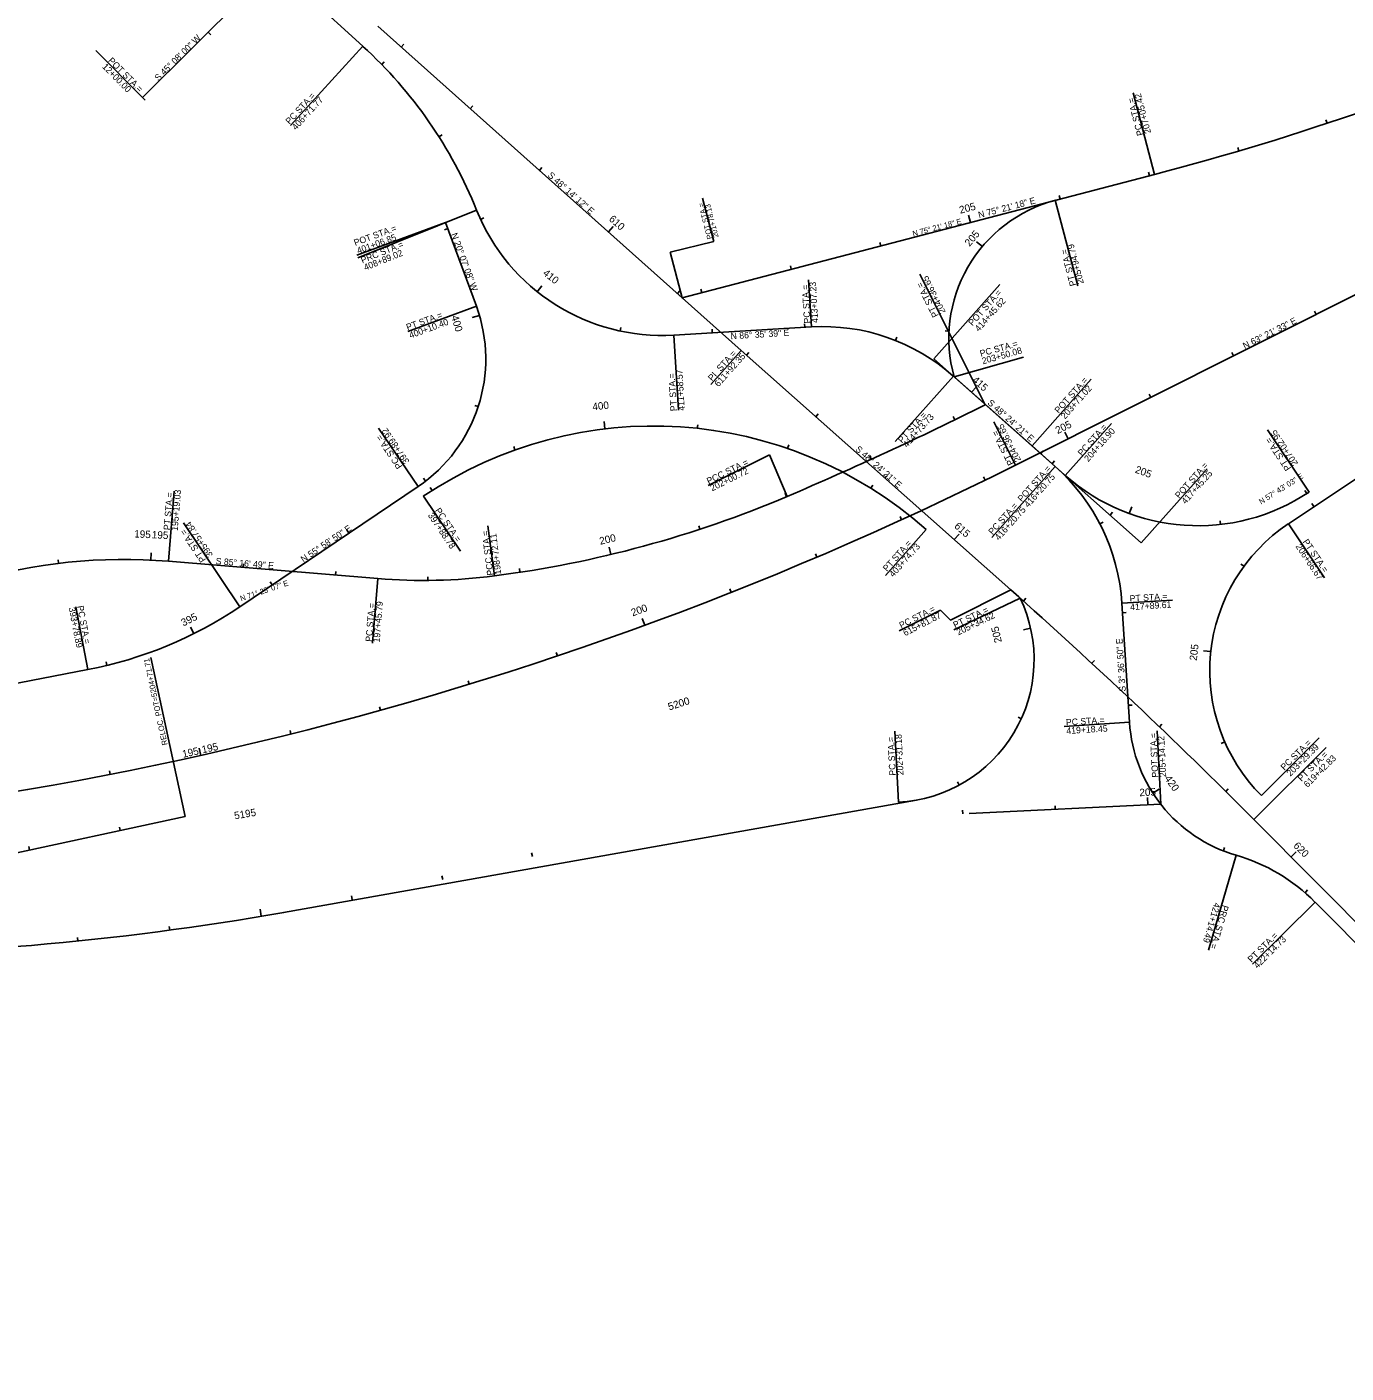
# Model space of a CAD drawing. Extents: x 1944333 to 1978554, y 788952 to 827675.
# Drawn here: x 1970666 to 1972091, y 801731 to 803186 of the extents above; entities that cross this region are included whole.
import ezdxf

# ---------------------------------------------------------------- set-up
doc = ezdxf.new("R2010")
doc.units = 0
for name, color, linetype in [('RD_HC_CL_Rel', 7, 'Continuous'), ('RD_HC_Data_Rel', 7, 'Continuous'), ('RD_HC_Data_Tic_Rel', 7, 'Continuous'), ('RD_HC_TX_Rel_Sta50', 7, 'Continuous')]:
    doc.layers.add(name, color=color, linetype=linetype)

msp = doc.modelspace()

# ---------------------------------------------------------------- linework, layer by layer
at = {"layer": 'RD_HC_CL_Rel'}
for p, q in [((1971733.6, 802712.2), (1977445.5, 805577.6)), ((1971733.6, 802712.2), (1977177.4, 805443.1)), ((1970666, 803495.5), (1971028.6, 803164.7)), ((1970933.3, 803251.6), (1970790.6, 803109.5)), ((1971044.7, 803186.4), (1971437.2, 802836)), ((1971373.4, 802893), (1971883.6, 803026.3)), ((1971151.2, 802883.8), (1971118, 802974.3)), ((1971364.6, 802852.6), (1971513, 802861.5)), ((1972028.2, 802648.8), (1972357, 802868.6)), ((1971437.2, 802836), (1971728.6, 802577.4)), ((1971645.3, 802827.1), (1971869.4, 802628.2)), ((1971666.4, 802808.4), (1971751.4, 802732.9)), ((1971751.4, 802732.9), (1971787.2, 802701.1)), ((1970895.8, 802559.2), (1971088.2, 802689.1)), ((1971824.7, 802648.6), (1971828.3, 802650.5)), ((1970818.6, 802608.3), (1971044.6, 802589.7)), ((1971848.5, 802562.9), (1971856.6, 802434.3)), ((1971849.2, 802552.5), (1971853.1, 802552.8)), ((1970421.7, 802431.5), (1970731.6, 802491.3)), ((1971855.5, 802452.7), (1971859.5, 802453)), ((1971881.8, 802357.7), (1971888.6, 802362)), ((1970943, 802228.9), (1971626.6, 802350.3)), ((1970416.5, 802242), (1970836.6, 802332.4)), ((1971683.3, 802335.8), (1971890.4, 802345.7)), ((1971990.8, 802329.4), (1972573.8, 801742.5)), ((1971949.8, 802297.9), (1971949.7, 802297.9)), ((1971958, 802295.4), (1971959.4, 802299.1)), ((1972046.2, 802250.2), (1972048.8, 802253.2)), ((1972057, 802240.1), (1972562.5, 801731.2))]:
    msp.add_line(p, q, dxfattribs=at)
for centre, radius, start, end in [((1971125.1, 805928.8), 3000, 284.6451, 293.8451), ((1970702.4, 802807.1), 484, 21.9066, 47.6252), ((1971351.8, 803068.3), 216, 201.9066, 273.4058), ((1971815.5, 802849.3), 154, 104.6451, 195.6897), ((1970995.3, 802826.7), 166, 304.0194, 20.119), ((1971525.6, 802649.9), 212, 48.4058, 93.4058), ((1970020.9, 806126.4), 3746.7, 293.033, 296.6408), ((1971342.3, 802310.5), 444, 48.4058, 124.0194), ((1970020.9, 806126.4), 3819.7, 269.5721, 296.6408), ((1970020.9, 806126.4), 3819.7, 269.5721, 296.6408), ((1971632.9, 802549.3), 216, 3.6139, 48.4058), ((1971930.6, 802862.7), 216, 228.4058, 303.7548), ((1971017.3, 803782.7), 1200, 277.3429, 293.033), ((1972134.3, 802490), 191, 123.7548, 224.9321), ((1970770.3, 802023.3), 587, 85.2802, 106.4681), ((1971094, 803187.6), 600, 265.2802, 277.3429), ((1971599.6, 802501.9), 154, 272.7416, 25.6376), ((1967911.4, 798277.1), 5750, 44.80908, 48.40581), ((1970647.4, 802927.2), 444, 280.9265, 304.0194), ((1972016.3, 802444.4), 160, 183.6139, 253.8155), ((1971916.5, 802100.6), 198, 44.8091, 73.8155), ((1970418.4, 805182.7), 3000, 269.5721, 280.0718)]:
    msp.add_arc(centre, radius, start, end, dxfattribs=at)
at = {"layer": 'RD_HC_Data_Rel'}
for p, q in [((1971028.6, 803164.7), (1970950.4, 803079)), ((1970740.2, 803160.1), (1970790.6, 803109.5)), ((1971883.6, 803026.3), (1971860.5, 803114.6)), ((1971151.4, 802987.7), (1971023.3, 802936.2)), ((1971407.6, 802953.7), (1971395.4, 803000.7)), ((1971776.5, 802998.3), (1971800.7, 802906)), ((1971118, 802974.3), (1971022.2, 802939.2)), ((1971407.6, 802953.7), (1971360.5, 802942.4)), ((1971373.4, 802893), (1971360.5, 802942.4)), ((1971700.9, 802777.4), (1971630.2, 802918.4)), ((1971513, 802861.5), (1971510, 802912.5)), ((1971645.3, 802827.1), (1971716.5, 802907.2)), ((1971151.2, 802883.8), (1971077.3, 802856.7)), ((1971364.6, 802852.6), (1971369.5, 802771.4)), ((1971437.2, 802836), (1971404.6, 802799.4)), ((1971667.2, 802807.7), (1971742.3, 802828.8)), ((1971666.4, 802808.4), (1971603.5, 802737.6)), ((1971751.4, 802732.9), (1971815.3, 802804.9)), ((1971733.6, 802712.2), (1971710.2, 802759)), ((1971787.2, 802701.1), (1971837.1, 802757.3)), ((1971088.2, 802689.1), (1971045.5, 802752.2)), ((1972050.6, 802683.1), (1972005.6, 802750.5)), ((1971401.6, 802690.3), (1971467.7, 802723.4)), ((1971486.8, 802678.4), (1971467.7, 802723.4)), ((1971776.3, 802710.8), (1971708.1, 802633.9)), ((1971773.1, 802713.7), (1971775.7, 802716.7)), ((1971869.4, 802628.2), (1971940.6, 802708.3)), ((1970818.6, 802608.3), (1970824.9, 802683.9)), ((1972048.2, 802681.5), (1972046, 802684.8)), ((1971093.9, 802678.5), (1971134, 802619.1)), ((1971856.4, 802659.8), (1971859.2, 802667.3)), ((1971954.9, 802648), (1971954.4, 802652)), ((1970895.8, 802559.2), (1970834.7, 802649.8)), ((1971170.7, 802592.5), (1971163.7, 802646.5)), ((1971637.1, 802642.5), (1971593, 802592.8)), ((1972028.2, 802648.8), (1972067.2, 802590.4)), ((1971044.6, 802589.7), (1971038.9, 802520)), ((1971738.5, 802568.6), (1971667, 802534.3)), ((1971848.5, 802562.9), (1971902.9, 802566.3)), ((1970731.6, 802491.3), (1970718.5, 802559.1)), ((1970836.6, 802332.4), (1970799.7, 802504.2)), ((1971856.6, 802434.3), (1971785.9, 802429.8)), ((1971607, 802348.1), (1971603.3, 802424.7)), ((1971890.4, 802345.7), (1971886.6, 802425)), ((1971990.8, 802329.4), (1972069.1, 802407.2)), ((1971999.1, 802355.1), (1972061.6, 802417.5)), ((1971876.3, 802345), (1971875.9, 802353)), ((1971971.7, 802290.7), (1971941.9, 802188.1)), ((1972057, 802240.1), (1971989.6, 802173.1))]:
    msp.add_line(p, q, dxfattribs=at)
for points in [[(1971728.6, 802577.4), (1971663.4, 802544.7), (1971652.6, 802555.4)], [(1971652.6, 802555.4), (1971608, 802533)]]:
    msp.add_lwpolyline(points, dxfattribs=at)
at = {"layer": 'RD_HC_Data_Tic_Rel'}
for p, q in [((1970861.5, 803180.1), (1970864.3, 803177.2)), ((1971070, 803163.9), (1971072.7, 803166.9)), ((1971048.9, 803145), (1971051.7, 803147.8)), ((1971048.9, 803145), (1971051.7, 803147.8)), ((1970790.6, 803109.5), (1970793.4, 803106.7)), ((1971144.6, 803097.3), (1971147.3, 803100.3)), ((1972070.1, 803081.5), (1972068.8, 803085.3)), ((1971110.8, 803066.8), (1971114.2, 803068.9)), ((1971110.8, 803066.8), (1971114.2, 803068.9)), ((1971974.7, 803051.6), (1971973.6, 803055.5)), ((1971219.2, 803030.7), (1971221.8, 803033.7)), ((1971878.3, 803024.9), (1971877.3, 803028.8)), ((1971781.6, 802999.6), (1971780.6, 803003.5)), ((1971155.8, 802977.6), (1971159.4, 802979.3)), ((1971684.8, 802974.3), (1971682.8, 802982.1)), ((1971120.3, 802967.9), (1971116.6, 802966.5)), ((1971293.8, 802964.1), (1971299.1, 802970)), ((1971588.1, 802949), (1971587.1, 802952.9)), ((1971697.7, 802948.5), (1971691.5, 802953.6)), ((1971491.3, 802923.8), (1971490.3, 802927.6)), ((1971216.9, 802899.6), (1971221.9, 802905.8)), ((1971368.4, 802897.5), (1971371, 802900.5)), ((1971394.6, 802898.5), (1971393.6, 802902.4)), ((1971154.4, 802873.9), (1971146.8, 802871.6)), ((1972058.4, 802875.1), (1972056.6, 802878.7)), ((1972058.4, 802875.1), (1972056.6, 802878.7)), ((1971306.4, 802857.1), (1971307.3, 802861)), ((1971406, 802855.1), (1971405.8, 802859.1)), ((1971505.8, 802861.1), (1971505.6, 802865)), ((1971661.7, 802857), (1971657.7, 802857.2)), ((1971603.9, 802846.9), (1971605.4, 802850.6)), ((1971443, 802830.9), (1971445.6, 802833.9)), ((1971969, 802830.3), (1971967.2, 802833.9)), ((1971969, 802830.3), (1971967.2, 802833.9)), ((1971686, 802791), (1971691.3, 802796.9)), ((1971686, 802791), (1971691.3, 802796.9)), ((1971879.6, 802785.4), (1971877.9, 802789)), ((1971879.6, 802785.4), (1971877.9, 802789)), ((1971153.2, 802775.4), (1971149.4, 802776.6)), ((1971290, 802751.4), (1971289.1, 802759.3)), ((1971389.8, 802751.9), (1971390.3, 802755.9)), ((1971517.8, 802764.5), (1971520.4, 802767.5)), ((1971668.1, 802761.2), (1971666.3, 802764.8)), ((1971790.3, 802740.6), (1971786.7, 802747.8)), ((1971790.3, 802740.6), (1971786.7, 802747.8)), ((1971192.9, 802728.6), (1971191.6, 802732.3)), ((1971487.2, 802730.2), (1971488.5, 802734)), ((1971760.8, 802724.6), (1971763.5, 802727.6)), ((1971760.8, 802724.6), (1971763.5, 802727.6)), ((1971760.8, 802724.6), (1971763.5, 802727.6)), ((1971760.8, 802724.6), (1971763.5, 802727.6)), ((1971760.8, 802724.6), (1971763.5, 802727.6)), ((1971577.7, 802718.4), (1971576, 802722.1)), ((1971773.1, 802713.7), (1971775.7, 802716.7)), ((1971096.3, 802695), (1971093.9, 802698.1)), ((1971592.5, 802698.1), (1971595.2, 802701.1)), ((1971700.8, 802695.9), (1971699, 802699.5)), ((1971700.8, 802695.9), (1971699, 802699.5)), ((1971103.3, 802684.6), (1971101.1, 802688)), ((1971486.2, 802678.1), (1971484.6, 802681.8)), ((1971577.3, 802687.2), (1971579.4, 802690.6)), ((1972055.9, 802667.4), (1972053.7, 802670.7)), ((1971610.4, 802653.1), (1971608.8, 802656.8)), ((1971610.4, 802653.1), (1971608.8, 802656.8)), ((1971835.6, 802658.2), (1971838.2, 802661.2)), ((1971835.6, 802658.2), (1971838.2, 802661.2)), ((1971835.6, 802658.2), (1971838.2, 802661.2)), ((1971013.6, 802638.8), (1971011.4, 802642.1)), ((1971392.6, 802642.9), (1971391.3, 802646.7)), ((1971667.3, 802631.7), (1971672.6, 802637.7)), ((1971296.4, 802615.6), (1971294.6, 802623.4)), ((1970699.8, 802606.1), (1970699.4, 802610)), ((1970799.7, 802609.6), (1970800.1, 802617.6)), ((1971519, 802612.7), (1971517.4, 802616.4)), ((1971519, 802612.7), (1971517.4, 802616.4)), ((1970899.3, 802601.7), (1970899.7, 802605.6)), ((1970999, 802593.4), (1970999.3, 802597.4)), ((1971198.3, 802596.4), (1971197.7, 802600.4)), ((1971980.3, 802603), (1971977, 802605.3)), ((1970930.7, 802582.8), (1970928.5, 802586.1)), ((1971098.8, 802587.6), (1971098.8, 802591.6)), ((1971426.5, 802574.7), (1971425, 802578.4)), ((1971426.5, 802574.7), (1971425, 802578.4)), ((1971742.1, 802565.3), (1971744.8, 802568.3)), ((1971742.1, 802565.3), (1971744.8, 802568.3)), ((1970845.9, 802530.1), (1970842.3, 802537.2)), ((1971333, 802539.1), (1971330.3, 802546.6)), ((1971333, 802539.1), (1971330.3, 802546.6)), ((1971749.8, 802535.9), (1971742, 802534.2)), ((1971238.7, 802506), (1971237.4, 802509.8)), ((1971238.7, 802506), (1971237.4, 802509.8)), ((1971944.4, 802510.8), (1971936.5, 802511.7)), ((1970752.2, 802495.8), (1970751.2, 802499.7)), ((1971816.1, 802498.1), (1971818.8, 802501)), ((1971143.5, 802475.4), (1971142.3, 802479.2)), ((1971143.5, 802475.4), (1971142.3, 802479.2)), ((1971047.5, 802447.2), (1971046.4, 802451.1)), ((1971047.5, 802447.2), (1971046.4, 802451.1)), ((1971739.8, 802438.2), (1971736.2, 802439.9)), ((1970950.9, 802421.6), (1970949.9, 802425.5)), ((1970950.9, 802421.6), (1970949.9, 802425.5)), ((1971888.9, 802429.5), (1971891.7, 802432.4)), ((1970853.6, 802398.5), (1970851.8, 802406.3)), ((1970853.6, 802398.5), (1970851.8, 802406.3)), ((1971959.5, 802413.1), (1971955.8, 802411.5)), ((1970755.7, 802378), (1970754.9, 802381.9)), ((1970755.7, 802378), (1970754.9, 802381.9)), ((1971672.7, 802366.4), (1971670.8, 802369.9)), ((1971960.5, 802359.7), (1971963.3, 802362.6)), ((1971676.5, 802335.4), (1971676.3, 802339.4)), ((1971776.4, 802340.2), (1971776.2, 802344.2)), ((1970766.5, 802317.3), (1970765.7, 802321.2)), ((1970668.7, 802296.3), (1970667.9, 802300.2)), ((1971211.7, 802289.5), (1971210.6, 802293.3)), ((1972031.1, 802288.9), (1972036.8, 802294.5)), ((1971114.8, 802264.6), (1971113.9, 802268.5)), ((1971017.2, 802243), (1971016.4, 802247)), ((1970918.9, 802224.7), (1970917.5, 802232.6)), ((1970720.7, 802198), (1970720.3, 802201.9)), ((1970820, 802209.7), (1970819.5, 802213.6))]:
    msp.add_line(p, q, dxfattribs=at)

# ---------------------------------------------------------------- texts
at = {"layer": 'RD_HC_CL_Rel'}
for s, rotation, p in [('PC STA.=', 48.4058, (1971708.7, 802636.4)), ('416+20.75', 48.4058, (1971715.6, 802630.3)), ('S 3%%d 36\' 50" E', 93.6139, (1971852.6, 802467.6)), ('PC STA.=', 3.6139, (1971788.2, 802430.8)), ('419+18.45', 3.6139, (1971788.7, 802421.6)), ('421+14.49', 253.8155, (1971948.3, 802240)), ('PRC STA.=', 253.8155, (1971957.2, 802237.4)), ('PT STA.=', 44.8091, (1971988.4, 802174.3)), ('422+14.73', 44.8091, (1971994.9, 802167.8))]:
    msp.add_text(s, height=7, rotation=rotation, dxfattribs=at).set_placement(p)
at = {"layer": 'RD_HC_Data_Rel'}
for s, height, rotation, p in [('S 45%%d 08\' 00" W', 7, 44.8665, (1970807.8, 803126.7)), ('POT STA.=', 7, 314.8665, (1970752.9, 803148.6)), ('12+00.00', 7, 314.8665, (1970746.4, 803142.1)), ('PC STA.=', 7, 47.6252, (1970949.5, 803079.8)), ('406+71.77', 7, 47.6252, (1970956.3, 803073.6)), ('PC STA.=', 7, 104.6451, (1971871.8, 803069.1)), ('207+05.42', 7, 104.6451, (1971880, 803071.3)), ('S 48%%d 14\' 12" E', 7, 318.2368, (1971227.7, 803024.5)), ('N 75%%d 21\' 18" E', 7, 14.6451, (1971694.2, 802979)), ('POT STA.=', 5.67, 104.6451, (1971406.3, 802957.1)), ('201+78.13', 5.67, 104.6451, (1971412.9, 802958.8)), ('N 75%%d 21\' 18" E', 6, 14.6451, (1971623.1, 802959.2)), ('POT STA.=', 7, 20.119, (1971020.4, 802948.9)), ('401+06.85', 7, 20.119, (1971023.6, 802940.3)), ('N 20%%d 07\' 08" W', 7, 290.119, (1971123.7, 802961.6)), ('PRC STA.=', 7, 21.9066, (1971028.1, 802930)), ('408+89.02', 7, 21.9066, (1971031.2, 802922.2)), ('PT STA.=', 7, 104.6451, (1971799.3, 802906.6)), ('205+94.79', 7, 104.6451, (1971807.4, 802908.7)), ('204+36.65', 7, 116.6408, (1971658.3, 802877.7)), ('PC STA.=', 7, 93.4058, (1971512.1, 802865.5)), ('413+07.23', 7, 93.4058, (1971520.5, 802866)), ('PT STA.=', 7, 116.6408, (1971650.7, 802874)), ('POT STA.=', 7, 48.4058, (1971687.1, 802862)), ('414+45.62', 7, 48.4058, (1971694, 802855.9)), ('PT STA.=', 7, 20.119, (1971076.9, 802857.6)), ('400+10.40', 7, 20.119, (1971080, 802848.9)), ('N 63%%d 21\' 33" E', 7, 26.6408, (1971981.2, 802837.5)), ('N 86%%d 35\' 39" E', 7, 3.4058, (1971426, 802848.1)), ('PC STA.=', 7, 15.6897, (1971696.1, 802829.2)), ('PI  STA.=', 7, 48.2368, (1971405.8, 802802.4)), ('611+92.35', 7, 48.2368, (1971412.7, 802796.2)), ('203+50.08', 7, 15.6897, (1971698.3, 802821.1)), ('411+58.57', 7, 93.4058, (1971376.3, 802771.2)), ('PT STA.=', 7, 93.4058, (1971367.9, 802770.7)), ('POT STA.=', 7, 48.4058, (1971780.2, 802767.5)), ('203+71.02', 7, 48.4058, (1971787, 802761.4)), ('S 48%%d 24\' 21" E', 7, 318.4058, (1971702.7, 802778.6)), ('PT STA.=', 7, 48.4058, (1971611.1, 802735.3)), ('414+73.73', 7, 48.4058, (1971616.4, 802730.6)), ('204+36.65', 7, 116.6408, (1971739.7, 802717.7)), ('PC STA.=', 7, 48.4058, (1971805.2, 802721.4)), ('PC STA.=', 7, 124.0194, (1971071.6, 802711)), ('397+89.92', 7, 124.0194, (1971079.2, 802716.2)), ('PT STA.=', 7, 116.6408, (1971732.2, 802714)), ('204+18.90', 7, 48.4058, (1971812.1, 802715.3)), ('PT STA.=', 7, 123.7548, (1972031.4, 802708.9)), ('207+02.95', 7, 123.7548, (1972039.1, 802714)), ('S 48%%d 24\' 21" E', 7, 318.4058, (1971559.9, 802728.5)), ('PCC STA.=', 7, 26.4818, (1971402.1, 802691.3)), ('POT STA.=', 7, 48.4058, (1971740.4, 802671.9)), ('205', 8, 339.9195, (1971862, 802704.3)), ('POT STA.=', 7, 48.4058, (1971910.3, 802675.6)), ('202+00.72', 7, 26.4818, (1971405.9, 802683.8)), ('416+20.75', 7, 48.4058, (1971747.3, 802665.8)), ('417+45.25', 7, 48.4058, (1971917.2, 802669.5)), ('N 57%%d 43\' 03" E', 6, 32.2824, (1971998.8, 802669.5)), ('PT STA.=', 7, 85.2802, (1970820.2, 802641.7)), ('195+19.03', 7, 85.2802, (1970828.6, 802641)), ('PC STA.=', 7, 304.0194, (1971106.1, 802663.1)), ('397+88.78', 7, 304.0194, (1971098.5, 802657.9)), ('PT STA.=', 7, 124.0194, (1970859.4, 802610)), ('395+57.84', 7, 124.0194, (1970867, 802615.2)), ('N 55%%d 58\' 50" E', 7, 34.0194, (1970964.4, 802606.8)), ('PCC STA.=', 7, 97.0479, (1971169.8, 802593.4)), ('198+72.11', 7, 97.0479, (1971178.1, 802594.4)), ('PT STA.=', 7, 48.4058, (1971594.7, 802596.7)), ('403+74.73', 7, 48.4058, (1971601.5, 802590.6)), ('206+66.67', 7, 303.7548, (1972035.7, 802624.3)), ('PT STA.=', 7, 303.7548, (1972043.4, 802629.4)), ('S 85%%d 16\' 49" E', 7, 355.2802, (1970869.4, 802605.2)), ('N 71%%d 23\' 07" E', 6, 18.6146, (1970897.2, 802565)), ('197+45.79', 7, 85.2802, (1971046.7, 802520.4)), ('393+78.89', 7, 280.9265, (1970710.8, 802558)), ('PC STA.=', 7, 280.9265, (1970719.8, 802559.7)), ('PC STA.=', 7, 85.2802, (1971038.3, 802521.1)), ('PC STA.=', 7, 27.2288, (1971610.1, 802535.4)), ('615+81.87', 7, 27.2288, (1971614.3, 802527.2)), ('PT STA.=', 7, 25.6376, (1971668.2, 802535.8)), ('205+34.62', 7, 25.6376, (1971671.8, 802528.2)), ('RELOC. POT=5204+71.71', 6, 102.1339, (1970817.8, 802410.2)), ('202+31.18', 7, 92.7416, (1971612.6, 802377.2)), ('POT STA.=', 7, 92.7416, (1971887.9, 802374.8)), ('205+14.12', 7, 92.7416, (1971896.3, 802375.2)), ('PC STA.=', 7, 92.7416, (1971604.2, 802376.8)), ('PC STA.=', 7, 44.9321, (1972023.9, 802381.9)), ('203+29.39', 7, 44.9321, (1972030.3, 802375.4)), ('PT STA.=', 7, 44.8091, (1972042.4, 802369.9)), ('619+42.83', 7, 44.8091, (1972048.9, 802363.4)), ('205', 8, 2.7416, (1971867.5, 802354.4))]:
    msp.add_text(s, height=height, rotation=rotation, dxfattribs=at).set_placement(p)
at = {"layer": 'RD_HC_Data_Tic_Rel'}
for s, p in [('PT STA.=', (1971857, 802564.5)), ('417+89.61', (1971857.6, 802555.4))]:
    msp.add_text(s, height=7, rotation=3.6139, dxfattribs=at).set_placement(p)
at = {"layer": 'RD_HC_TX_Rel_Sta50'}
for s, rotation, p in [('205', 14.6451, (1971673.9, 802983.8)), ('610', 318.2368, (1971293.7, 802977.1)), ('205', 49.9119, (1971683.9, 802947.9)), ('410', 321.345, (1971222.3, 802918.4)), ('400', 286.5302, (1971123.9, 802872.7)), ('415', 318.4058, (1971686, 802803.1)), ('400', 6.7626, (1971277, 802771.2)), ('205', 26.6408, (1971779, 802745.6)), ('195', 357.1377, (1970781.5, 802634.1)), ('195', 357.1377, (1970800.5, 802633.2)), ('200', 13.4491, (1971285.1, 802626.1)), ('615', 318.4058, (1971666.7, 802645.3)), ('395', 26.5553, (1970834.7, 802537.8)), ('200', 20.091, (1971320, 802548.7)), ('205', 102.7562, (1971718.8, 802521.2)), ('205', 83.7528, (1971929.3, 802500.6)), ('5200', 17.5154, (1971359.6, 802447.1)), ('195', 12.591, (1970834.5, 802395.9)), ('195', 12.591, (1970855.5, 802400.7)), ('420', 305.1032, (1971894.1, 802373.5)), ('5195', 9.6029, (1970890.3, 802329.4)), ('620', 314.8091, (1972033, 802300.3))]:
    msp.add_text(s, height=8, rotation=rotation, dxfattribs=at).set_placement(p)

doc.saveas('drawing.dxf')
